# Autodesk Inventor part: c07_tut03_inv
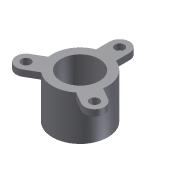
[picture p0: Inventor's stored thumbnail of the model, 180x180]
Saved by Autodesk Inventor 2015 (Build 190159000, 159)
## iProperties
Created: 2010-03
Part Number: c07_tut03_inv
Document SubType Name: Modeling
Designer: CADSoft
Density: 1 g/cm^3
Material: Generic
Appearance: Default
Author: CADSoft
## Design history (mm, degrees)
sketch "Sketch1"
  geometry: C1 r 97 at (0, 0); C2 r 140 at (0, 0); 1 further point
  constraints: 2 centre point, 2 coincident
  dimensions: "d0" = 194 diameter of C1; "d1" = 280 diameter of C2
extrude "Extrusion1" new body sketch "Sketch1" stored distance "d2" = 225; taper "d3" = 0 deg
pattern_circular "Circular Pattern2" dims angle "d38" = 360 deg
body "Solid1"
sketch "Sketch5"
  geometry: L1 (-50, 200)-(-50, 130.767); L2 (50, 200)-(50, 130.767); L3 (0, 0)-(0, 306.095); C1 r 97 at (0, 0) reference; C2 r 23.5 at (0, 200); A1 r 140 centre (0, 0) between (-50, 130.767) and (50, 130.767) reference; A2 r 50 centre (0, 200) between (50, 200) and (-50, 200); A3 r 140 centre (0, 0) between (50, 130.767) and (-50, 130.767)
  constraints: 7 point on circle, 6 end point, 3 centre point, 2 coincident, 2 tangent, 1 other
  dimensions: "d32" = 200 distance of A2.centre C1.centre; "d33" = 50 radius of A2; "d34" = 47 diameter of C2
extrude "Extrusion2" join sketch "Sketch5" distance "d35" = 32; taper "d36" = 0 deg
